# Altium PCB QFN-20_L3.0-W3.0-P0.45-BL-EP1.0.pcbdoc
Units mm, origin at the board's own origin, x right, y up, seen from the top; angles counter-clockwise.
Board outline 16.3 x 16.48 mm, 2 copper layers (Top Layer, Bottom Layer), stack 0 mm thick; 1 components, 0 nets, 21 pads, 0 vias.
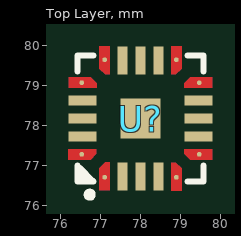
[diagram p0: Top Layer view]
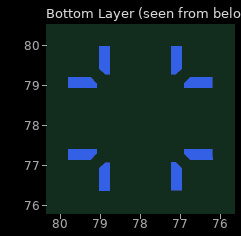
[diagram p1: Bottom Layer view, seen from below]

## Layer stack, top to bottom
Top Layer: signal copper (thickness not stored)
Bottom Layer: signal copper (thickness not stored)

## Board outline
86.151,69.85 69.85,69.85 69.85,86.332 86.151,86.332

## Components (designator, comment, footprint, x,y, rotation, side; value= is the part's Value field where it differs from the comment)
U? "" QFN-20_L3.0-W3.0-P0.45-BL-EP1.0 78,78.18 r0 top

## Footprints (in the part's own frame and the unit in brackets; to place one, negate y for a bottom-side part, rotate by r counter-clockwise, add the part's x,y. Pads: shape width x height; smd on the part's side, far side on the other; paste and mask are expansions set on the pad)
QFN-20_L3.0-W3.0-P0.45-BL-EP1.0 [mm]
  round 0.121 smd: 1(-0.895,-1.469) 5(0.896,-1.469) 6(1.469,-0.896) 10(1.469,0.894) 11(0.895,1.469) 15(-0.895,1.469) 16(-1.468,0.895) 20(-1.469,-0.896)
  rect 0.252x0.7 smd paste-100 mask+0.05: 2(-0.45,-1.45) 3(0,-1.45) 4(0.45,-1.45) 12(0.45,1.45) 13(0,1.45) 14(-0.45,1.45)
  rect 0.7x0.252 smd paste-100 mask+0.05: 7(1.45,-0.45) 8(1.45,0) 9(1.45,0.45) 17(-1.45,0.45) 18(-1.45,0) 19(-1.45,-0.45)
  rect 1x1 smd paste-100 mask+0.05: 21(0,0)
  Top Layer region: -1.799,1.026 -1.244,1.026 -1.099,0.882 -1.099,0.882 -1.099,0.774 -1.799,0.774 -1.799,0.903
  Top Layer region: -1.026,1.801 -1.026,1.245 -0.882,1.1 -0.882,1.1 -0.774,1.1 -0.774,1.8 -0.903,1.8
  Top Layer region: 1.026,1.801 1.026,1.245 0.881,1.1 0.881,1.1 0.774,1.1 0.774,1.8 0.903,1.8
  Top Layer region: 1.8,1.025 1.244,1.025 1.1,0.881 1.1,0.881 1.1,0.773 1.8,0.773 1.8,0.903
  Top Layer region: 1.8,-1.027 1.244,-1.027 1.1,-0.882 1.1,-0.882 1.1,-0.774 1.8,-0.774 1.8,-0.904
  Top Layer region: 1.027,-1.801 1.027,-1.245 0.882,-1.1 0.882,-1.1 0.774,-1.1 0.774,-1.8 0.904,-1.8
  Top Layer region: -1.026,-1.8 -1.026,-1.244 -0.882,-1.1 -0.882,-1.099 -0.774,-1.099 -0.774,-1.799 -0.903,-1.799
  Top Layer region: -1.8,-1.027 -1.245,-1.027 -1.1,-0.882 -1.1,-0.882 -1.1,-0.774 -1.8,-0.774 -1.8,-0.904
  Bottom Layer region: -1.799,1.026 -1.244,1.026 -1.099,0.882 -1.099,0.882 -1.099,0.774 -1.799,0.774 -1.799,0.903
  Bottom Layer region: -1.026,1.801 -1.026,1.245 -0.882,1.1 -0.882,1.1 -0.774,1.1 -0.774,1.8 -0.903,1.8
  Bottom Layer region: 1.026,1.801 1.026,1.245 0.881,1.1 0.881,1.1 0.774,1.1 0.774,1.8 0.903,1.8
  Bottom Layer region: 1.8,1.025 1.244,1.025 1.1,0.881 1.1,0.881 1.1,0.773 1.8,0.773 1.8,0.903
  Bottom Layer region: 1.8,-1.027 1.244,-1.027 1.1,-0.882 1.1,-0.882 1.1,-0.774 1.8,-0.774 1.8,-0.904
  Bottom Layer region: 1.027,-1.801 1.027,-1.245 0.882,-1.1 0.882,-1.1 0.774,-1.1 0.774,-1.8 0.904,-1.8
  Bottom Layer region: -1.026,-1.8 -1.026,-1.244 -0.882,-1.1 -0.882,-1.099 -0.774,-1.099 -0.774,-1.799 -0.903,-1.799
  Bottom Layer region: -1.8,-1.027 -1.245,-1.027 -1.1,-0.882 -1.1,-0.882 -1.1,-0.774 -1.8,-0.774 -1.8,-0.904
  Multi-Layer region: -1.799,1.026 -1.244,1.026 -1.099,0.882 -1.099,0.882 -1.099,0.774 -1.799,0.774 -1.799,0.903
  Multi-Layer region: -1.026,1.801 -1.026,1.245 -0.882,1.1 -0.882,1.1 -0.774,1.1 -0.774,1.8 -0.903,1.8
  Multi-Layer region: 1.026,1.801 1.026,1.245 0.881,1.1 0.881,1.1 0.774,1.1 0.774,1.8 0.903,1.8
  Multi-Layer region: 1.8,1.025 1.244,1.025 1.1,0.881 1.1,0.881 1.1,0.773 1.8,0.773 1.8,0.903
  Multi-Layer region: 1.8,-1.027 1.244,-1.027 1.1,-0.882 1.1,-0.882 1.1,-0.774 1.8,-0.774 1.8,-0.904
  Multi-Layer region: 1.027,-1.801 1.027,-1.245 0.882,-1.1 0.882,-1.1 0.774,-1.1 0.774,-1.8 0.904,-1.8
  Multi-Layer region: -1.026,-1.8 -1.026,-1.244 -0.882,-1.1 -0.882,-1.099 -0.774,-1.099 -0.774,-1.799 -0.903,-1.799
  Multi-Layer region: -1.8,-1.027 -1.245,-1.027 -1.1,-0.882 -1.1,-0.882 -1.1,-0.774 -1.8,-0.774 -1.8,-0.904
  silkscreen extent -1.58,-1.98 1.58,1.58

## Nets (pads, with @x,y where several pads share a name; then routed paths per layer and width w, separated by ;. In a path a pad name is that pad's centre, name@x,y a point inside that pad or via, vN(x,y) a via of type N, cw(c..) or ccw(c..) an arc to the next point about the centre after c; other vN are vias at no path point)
pads on no net: U?.1 U?.2 U?.3 U?.4 U?.5 U?.6 U?.7 U?.8 U?.9 U?.10 U?.11 U?.12 U?.13 U?.14 U?.15 U?.16 U?.17 U?.18 U?.19 U?.20 U?.21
